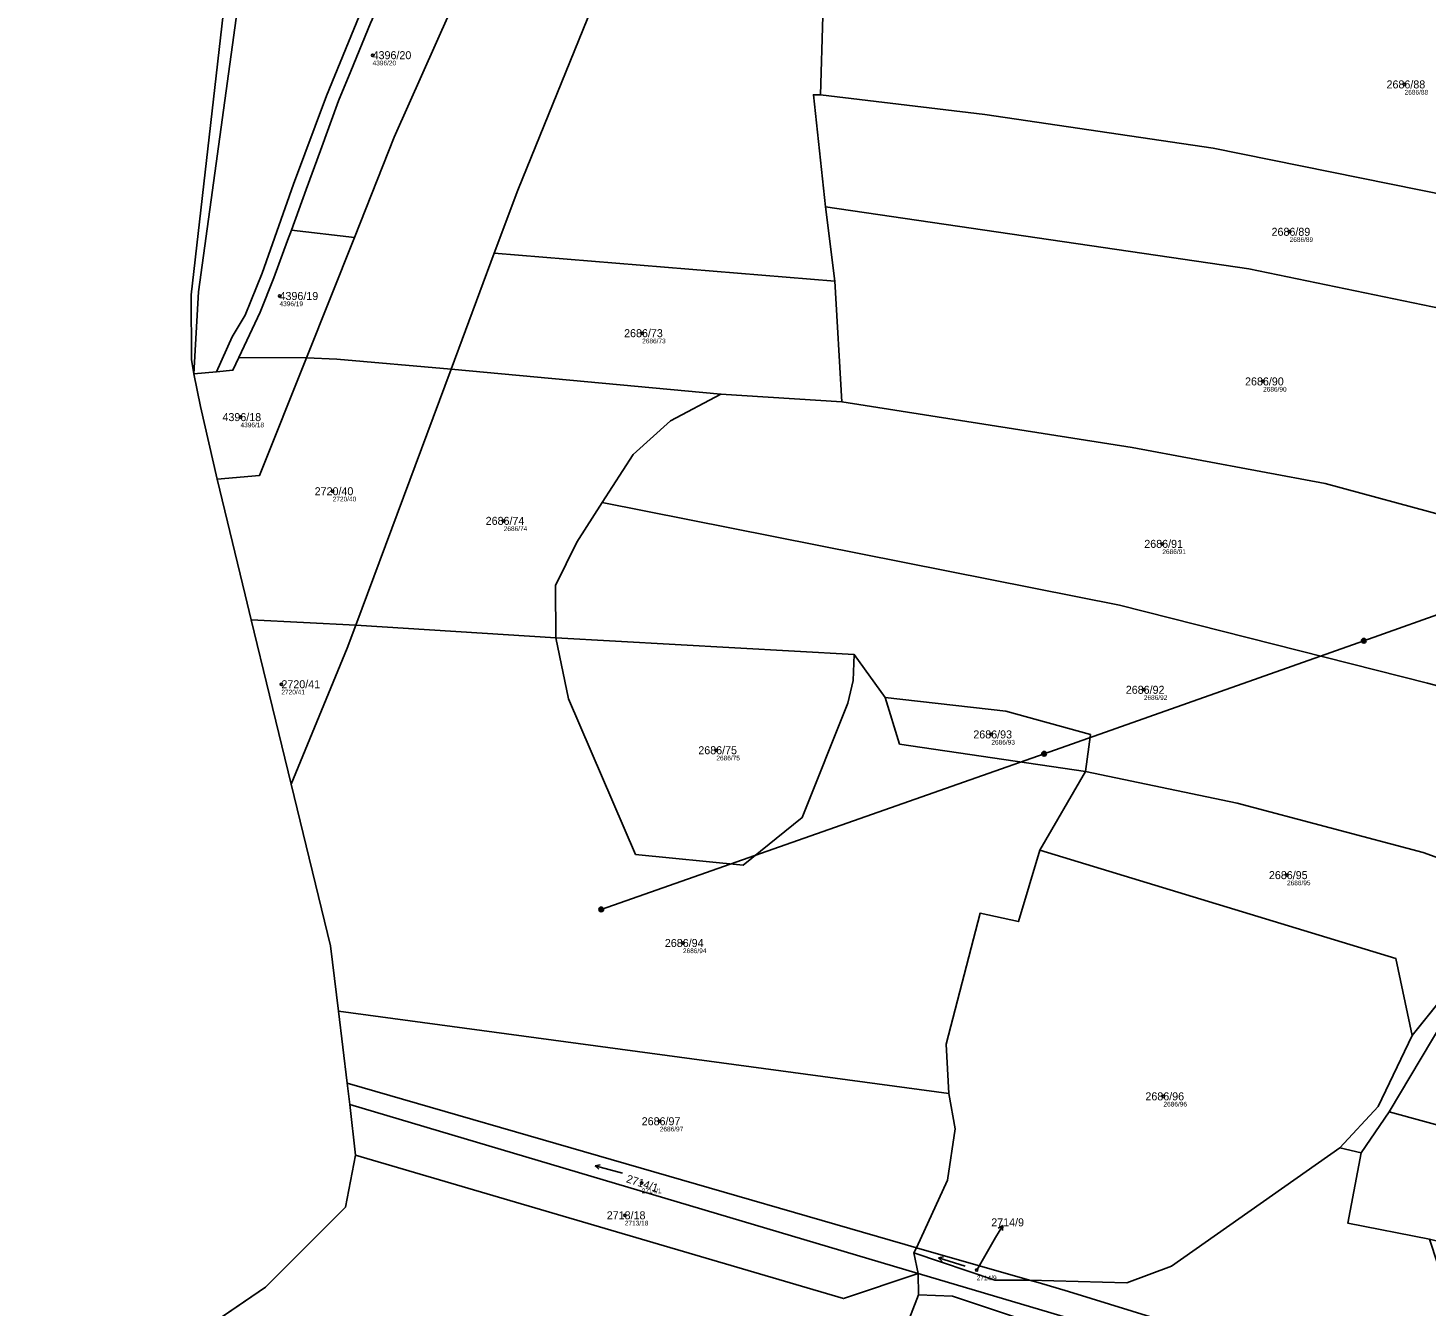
# Model space of a CAD drawing. Extents: x -739214 to -733252, y -1147612 to -1142842.
# Drawn here: x -737891.9 to -737595, y -1145670.6 to -1145399 of the extents above; entities that cross this region are included whole.
import ezdxf

# ---------------------------------------------------------------- set-up
doc = ezdxf.new("R2010")
doc.units = 0
for name, color, linetype in [('Definiční body', 7, 'Continuous'), ('Hranice parcel', 7, 'Continuous'), ('Parcelní čísla', 7, 'Continuous'), ('Polygon ku', 7, 'Continuous'), ('Polygon parcely', 7, 'Continuous'), ('Pop  PČ popisy', 7, 'Continuous'), ('Poz předměty', 7, 'Continuous'), ('Značky kultur', 7, 'Continuous')]:
    doc.layers.add(name, color=color, linetype=linetype)

msp = doc.modelspace()

# ---------------------------------------------------------------- linework, layer by layer
at = {"layer": 'Definiční body'}
for centre in [(-737818.71, -1145404.81), (-737599.53, -1145411.02), (-737623.95, -1145442.33), (-737838.48, -1145455.97), (-737761.46, -1145463.87), (-737629.58, -1145474.12), (-737846.76, -1145481.7), (-737827.18, -1145497.45), (-737790.86, -1145503.74), (-737650.98, -1145508.63), (-737838.08, -1145538.45), (-737654.91, -1145539.63), (-737687.29, -1145549.11), (-737745.7, -1145552.47), (-737624.51, -1145579), (-737752.8, -1145593.42), (-737650.74, -1145626), (-737757.72, -1145631.29), (-737761.57, -1145644.42), (-737765.14, -1145651.27), (-737690.41, -1145662.91)]:
    msp.add_circle(centre, 0.25, dxfattribs=at)
at = {"layer": 'Hranice parcel'}
for p, q in [((-737720.56, -1145452.83), (-737722.54, -1145437)), ((-737822.59, -1145443.55), (-737835.97, -1145442.01)), ((-737822.59, -1145443.55), (-737832.76, -1145469.11)), ((-737802.04, -1145471.5), (-737792.88, -1145446.87)), ((-737792.88, -1145446.87), (-737720.56, -1145452.83)), ((-737719.05, -1145478.43), (-737720.56, -1145452.83)), ((-737832.76, -1145469.11), (-737847.1, -1145469.03)), ((-737832.76, -1145469.11), (-737842.7, -1145494.1)), ((-737851.89, -1145472.08), (-737856.65, -1145472.54)), ((-737822.28, -1145525.91), (-737802.04, -1145471.5)), ((-737802.04, -1145471.5), (-737744.75, -1145476.81)), ((-737744.75, -1145476.81), (-737719.05, -1145478.43)), ((-737842.7, -1145494.1), (-737851.75, -1145494.89)), ((-737851.75, -1145494.89), (-737845.78, -1145519.46)), ((-737845.78, -1145519.46), (-737844.49, -1145524.74)), ((-737844.49, -1145524.74), (-737822.28, -1145525.91)), ((-737824.1, -1145530.8), (-737822.28, -1145525.91)), ((-737822.28, -1145525.91), (-737779.78, -1145528.62)), ((-737716.46, -1145532.13), (-737779.78, -1145528.62)), ((-737835.99, -1145559.66), (-737824.1, -1145530.8)), ((-737716.46, -1145532.13), (-737709.84, -1145541.29)), ((-737676.97, -1145573.7), (-737667.29, -1145556.98)), ((-737835.99, -1145559.66), (-737827.63, -1145594.05)), ((-737597.9, -1145613.1), (-737573.23, -1145582.26)), ((-737827.63, -1145594.05), (-737825.96, -1145607.93)), ((-737825.96, -1145607.93), (-737696.36, -1145625.39)), ((-737825.96, -1145607.93), (-737824.12, -1145623.17)), ((-737602.82, -1145629.32), (-737589.22, -1145606.52)), ((-737824.12, -1145623.17), (-737823.54, -1145627.71)), ((-737823.54, -1145627.71), (-737822.34, -1145638.53)), ((-737702.86, -1145663.63), (-737823.54, -1145627.71)), ((-737608.78, -1145638.02), (-737602.82, -1145629.32)), ((-737613.3, -1145636.92), (-737608.78, -1145638.02)), ((-737703.74, -1145659.28), (-737703.22, -1145658.15)), ((-737702.86, -1145663.63), (-737703.74, -1145659.28)), ((-737703.22, -1145658.15), (-737679.19, -1145665.04)), ((-737702.86, -1145663.63), (-737702.8, -1145668.15)), ((-737841.45, -1145666.51), (-737891.91, -1145700.99))]:
    msp.add_line(p, q, dxfattribs=at)
for points in [[(-737820.98, -1145248.16), (-737839.51, -1145313.31), (-737844.19, -1145341.49), (-737857.22, -1145455.75)], [(-737856.65, -1145472.54), (-737855.68, -1145455.08), (-737836.49, -1145315.56), (-737819.83, -1145253.02)], [(-737851.89, -1145472.08), (-737848.57, -1145464.61), (-737845.77, -1145460.03), (-737842.15, -1145451.1), (-737835.49, -1145432.24), (-737828.54, -1145413.46), (-737820.9, -1145394.95), (-737812.66, -1145376.69), (-737804.1, -1145358.6), (-737797.23, -1145339.83), (-737790.15, -1145321.11), (-737782.47, -1145302.64), (-737775.45, -1145283.92), (-737769.39, -1145267.89)], [(-737723.59, -1145413.2), (-737723.12, -1145396.55), (-737719.42, -1145368.93), (-737714.76, -1145352.17), (-737701.5, -1145354.38)], [(-737805.42, -1145365.82), (-737814.67, -1145388.16), (-737819.14, -1145398.03), (-737823.33, -1145408.23), (-737825.93, -1145414.53), (-737829.78, -1145425.05), (-737832.81, -1145433.33), (-737835.97, -1145442.01)], [(-737790.37, -1145368.76), (-737814.1, -1145422.2), (-737822.59, -1145443.55)], [(-737792.88, -1145446.87), (-737787.9, -1145433.5), (-737761.96, -1145369.63)], [(-737722.54, -1145437), (-737725.1, -1145413.2), (-737723.59, -1145413.2)], [(-737723.59, -1145413.2), (-737688.72, -1145417.44), (-737640.21, -1145424.55), (-737583.87, -1145435.95), (-737543.1, -1145448.28), (-737510.54, -1145463.81)], [(-737722.54, -1145437), (-737632.64, -1145450.18), (-737591.58, -1145458.72), (-737541.75, -1145472.73), (-737522.21, -1145480.38)], [(-737835.97, -1145442.01), (-737836.77, -1145444.19), (-737839.66, -1145452.12), (-737842.57, -1145459.44), (-737847.1, -1145469.03)], [(-737857.22, -1145455.75), (-737857.17, -1145469.44), (-737856.65, -1145472.54)], [(-737847.1, -1145469.03), (-737848.38, -1145471.74), (-737851.89, -1145472.08)], [(-737832.76, -1145469.11), (-737826.29, -1145469.39), (-737802.04, -1145471.5)], [(-737856.65, -1145472.54), (-737855.27, -1145479.41), (-737851.75, -1145494.89)], [(-737769.95, -1145499.87), (-737763.38, -1145489.61), (-737755.47, -1145482.51), (-737744.75, -1145476.81)], [(-737719.05, -1145478.43), (-737657.41, -1145488.14), (-737616.39, -1145495.81), (-737590.27, -1145502.9), (-737564.75, -1145511.61), (-737544.52, -1145520.75)], [(-737779.78, -1145528.62), (-737779.86, -1145517.46), (-737775.32, -1145508.26), (-737769.95, -1145499.87)], [(-737769.95, -1145499.87), (-737660.05, -1145521.67), (-737594.65, -1145538.21), (-737556.11, -1145548.41)], [(-737844.49, -1145524.74), (-737840.6, -1145540.74), (-737835.99, -1145559.66)], [(-737779.78, -1145528.62), (-737777.11, -1145541.57), (-737762.86, -1145574.62), (-737739.98, -1145576.92), (-737727.48, -1145566.78), (-737717.76, -1145542.47), (-737716.62, -1145537.65), (-737716.46, -1145532.13)], [(-737709.84, -1145541.29), (-737684.2, -1145544.15), (-737666.26, -1145549.14), (-737667.29, -1145556.98)], [(-737709.84, -1145541.29), (-737706.8, -1145551.18), (-737667.29, -1145556.98)], [(-737667.29, -1145556.98), (-737635.08, -1145563.73), (-737595.57, -1145574.22), (-737573.23, -1145582.26)], [(-737696.36, -1145625.39), (-737696.91, -1145614.89), (-737689.69, -1145587.09), (-737681.52, -1145588.86), (-737676.97, -1145573.7)], [(-737676.97, -1145573.7), (-737601.43, -1145596.68), (-737597.9, -1145613.1)], [(-737613.3, -1145636.92), (-737605.17, -1145628.13), (-737597.9, -1145613.1)], [(-737824.12, -1145623.17), (-737705.6, -1145657.47), (-737703.22, -1145658.15)], [(-737696.36, -1145625.39), (-737695, -1145632.88), (-737696.64, -1145643.79), (-737703.22, -1145658.15)], [(-737602.82, -1145629.32), (-737520.77, -1145651.77), (-737400.58, -1145678.49), (-737333.2, -1145691.3), (-737214.35, -1145710.13), (-737185.83, -1145716.79), (-737159.7, -1145725.21), (-737139.26, -1145734.98)], [(-737822.34, -1145638.53), (-737824.48, -1145649.51), (-737841.45, -1145666.51)], [(-737822.34, -1145638.53), (-737718.71, -1145668.96), (-737702.86, -1145663.63)], [(-737679.19, -1145665.04), (-737658.55, -1145665.61), (-737649.02, -1145662.11), (-737613.3, -1145636.92)], [(-737608.78, -1145638.02), (-737611.58, -1145652.96), (-737594.21, -1145656.35)], [(-737679.19, -1145665.04), (-737686.57, -1145665.05), (-737703.74, -1145659.28)], [(-737611.14, -1145716.76), (-737611.14, -1145701.1), (-737613.98, -1145694.1), (-737619.64, -1145689.1), (-737660.6, -1145676.2), (-737702.86, -1145663.63)], [(-737679.19, -1145665.04), (-737677.38, -1145665.56), (-737670.95, -1145667.46), (-737616.8, -1145684.16), (-737609.4, -1145690.18), (-737605.48, -1145699.2), (-737604.93, -1145717.85)], [(-737748.38, -1145708.23), (-737726.84, -1145698.64), (-737718.37, -1145693.53), (-737709.49, -1145685.57), (-737702.8, -1145668.15)], [(-737702.8, -1145668.15), (-737695.56, -1145668.48), (-737673.44, -1145675.79), (-737672.37, -1145683.37), (-737676.5, -1145694.97), (-737677.3, -1145705.14), (-737611.14, -1145716.76)]]:
    msp.add_lwpolyline(points, dxfattribs=at)
at = {"layer": 'Polygon ku'}
msp.add_lwpolyline([(-737844.19, -1145341.49), (-737857.22, -1145455.75), (-737857.17, -1145469.44), (-737856.65, -1145472.54), (-737855.27, -1145479.41), (-737851.75, -1145494.89), (-737845.78, -1145519.46), (-737844.49, -1145524.74), (-737840.6, -1145540.74), (-737835.99, -1145559.66), (-737827.63, -1145594.05), (-737825.96, -1145607.93), (-737824.12, -1145623.17), (-737823.54, -1145627.71), (-737822.34, -1145638.53), (-737824.48, -1145649.51), (-737841.45, -1145666.51), (-737891.91, -1145700.99)], dxfattribs=at)
at = {"layer": 'Polygon parcely'}
for points in [[(-737804.1, -1145358.6), (-737797.23, -1145339.83), (-737790.15, -1145321.11), (-737782.47, -1145302.64), (-737775.45, -1145283.92), (-737769.39, -1145267.89), (-737771.13, -1145267.35), (-737819.83, -1145253.02), (-737836.49, -1145315.56), (-737855.68, -1145455.08), (-737856.65, -1145472.54), (-737851.89, -1145472.08), (-737848.57, -1145464.61), (-737845.77, -1145460.03), (-737842.15, -1145451.1), (-737835.49, -1145432.24), (-737828.54, -1145413.46), (-737820.9, -1145394.95), (-737812.66, -1145376.69)], [(-737501.5, -1145453.26), (-737457.61, -1145416.9), (-737475.95, -1145408.95), (-737501.79, -1145402.86), (-737558.13, -1145387.45), (-737666.58, -1145363.91), (-737701.5, -1145354.38), (-737714.76, -1145352.17), (-737719.42, -1145368.93), (-737723.12, -1145396.55), (-737723.59, -1145413.2), (-737688.72, -1145417.44), (-737640.21, -1145424.55), (-737583.87, -1145435.95), (-737543.1, -1145448.28), (-737510.54, -1145463.81)], [(-737814.67, -1145388.16), (-737819.14, -1145398.03), (-737823.33, -1145408.23), (-737825.93, -1145414.53), (-737829.78, -1145425.05), (-737832.81, -1145433.33), (-737835.97, -1145442.01), (-737822.59, -1145443.55), (-737814.1, -1145422.2), (-737790.37, -1145368.76), (-737805.42, -1145365.82)], [(-737522.21, -1145480.38), (-737510.54, -1145463.81), (-737543.1, -1145448.28), (-737583.87, -1145435.95), (-737640.21, -1145424.55), (-737688.72, -1145417.44), (-737723.59, -1145413.2), (-737725.1, -1145413.2), (-737722.54, -1145437), (-737632.64, -1145450.18), (-737591.58, -1145458.72), (-737541.75, -1145472.73)], [(-737532.81, -1145497.63), (-737522.21, -1145480.38), (-737541.75, -1145472.73), (-737591.58, -1145458.72), (-737632.64, -1145450.18), (-737722.54, -1145437), (-737720.56, -1145452.83), (-737719.05, -1145478.43), (-737657.41, -1145488.14), (-737616.39, -1145495.81), (-737590.27, -1145502.9), (-737564.75, -1145511.61), (-737544.52, -1145520.75)], [(-737847.1, -1145469.03), (-737832.76, -1145469.11), (-737822.59, -1145443.55), (-737835.97, -1145442.01), (-737836.77, -1145444.19), (-737839.66, -1145452.12), (-737842.57, -1145459.44)], [(-737719.05, -1145478.43), (-737720.56, -1145452.83), (-737792.88, -1145446.87), (-737802.04, -1145471.5), (-737744.75, -1145476.81)], [(-737848.38, -1145471.74), (-737851.89, -1145472.08), (-737856.65, -1145472.54), (-737855.27, -1145479.41), (-737851.75, -1145494.89), (-737842.7, -1145494.1), (-737832.76, -1145469.11), (-737847.1, -1145469.03)], [(-737842.7, -1145494.1), (-737851.75, -1145494.89), (-737845.78, -1145519.46), (-737844.49, -1145524.74), (-737822.28, -1145525.91), (-737802.04, -1145471.5), (-737826.29, -1145469.39), (-737832.76, -1145469.11)], [(-737755.47, -1145482.51), (-737744.75, -1145476.81), (-737802.04, -1145471.5), (-737822.28, -1145525.91), (-737779.78, -1145528.62), (-737779.86, -1145517.46), (-737775.32, -1145508.26), (-737769.95, -1145499.87), (-737763.38, -1145489.61)], [(-737556.11, -1145548.41), (-737544.52, -1145520.75), (-737564.75, -1145511.61), (-737590.27, -1145502.9), (-737616.39, -1145495.81), (-737657.41, -1145488.14), (-737719.05, -1145478.43), (-737744.75, -1145476.81), (-737755.47, -1145482.51), (-737763.38, -1145489.61), (-737769.95, -1145499.87), (-737660.05, -1145521.67), (-737594.65, -1145538.21)], [(-737573.23, -1145582.26), (-737564.27, -1145566.85), (-737556.11, -1145548.41), (-737594.65, -1145538.21), (-737660.05, -1145521.67), (-737769.95, -1145499.87), (-737775.32, -1145508.26), (-737779.86, -1145517.46), (-737779.78, -1145528.62), (-737716.46, -1145532.13), (-737709.84, -1145541.29), (-737684.2, -1145544.15), (-737666.26, -1145549.14), (-737667.29, -1145556.98), (-737635.08, -1145563.73), (-737595.57, -1145574.22)], [(-737835.99, -1145559.66), (-737824.1, -1145530.8), (-737822.28, -1145525.91), (-737844.49, -1145524.74), (-737840.6, -1145540.74)], [(-737825.96, -1145607.93), (-737696.36, -1145625.39), (-737696.91, -1145614.89), (-737689.69, -1145587.09), (-737681.52, -1145588.86), (-737676.97, -1145573.7), (-737667.29, -1145556.98), (-737706.8, -1145551.18), (-737709.84, -1145541.29), (-737716.46, -1145532.13), (-737716.62, -1145537.65), (-737717.76, -1145542.47), (-737727.48, -1145566.78), (-737739.98, -1145576.92), (-737762.86, -1145574.62), (-737777.11, -1145541.57), (-737779.78, -1145528.62), (-737822.28, -1145525.91), (-737824.1, -1145530.8), (-737835.99, -1145559.66), (-737827.63, -1145594.05)], [(-737739.98, -1145576.92), (-737727.48, -1145566.78), (-737717.76, -1145542.47), (-737716.62, -1145537.65), (-737716.46, -1145532.13), (-737779.78, -1145528.62), (-737777.11, -1145541.57), (-737762.86, -1145574.62)], [(-737709.84, -1145541.29), (-737706.8, -1145551.18), (-737667.29, -1145556.98), (-737666.26, -1145549.14), (-737684.2, -1145544.15)], [(-737601.43, -1145596.68), (-737597.9, -1145613.1), (-737573.23, -1145582.26), (-737595.57, -1145574.22), (-737635.08, -1145563.73), (-737667.29, -1145556.98), (-737676.97, -1145573.7)], [(-737679.19, -1145665.04), (-737658.55, -1145665.61), (-737649.02, -1145662.11), (-737613.3, -1145636.92), (-737605.17, -1145628.13), (-737597.9, -1145613.1), (-737601.43, -1145596.68), (-737676.97, -1145573.7), (-737681.52, -1145588.86), (-737689.69, -1145587.09), (-737696.91, -1145614.89), (-737696.36, -1145625.39), (-737695, -1145632.88), (-737696.64, -1145643.79), (-737703.22, -1145658.15)], [(-737703.22, -1145658.15), (-737696.64, -1145643.79), (-737695, -1145632.88), (-737696.36, -1145625.39), (-737825.96, -1145607.93), (-737824.12, -1145623.17), (-737705.6, -1145657.47)], [(-737400.58, -1145678.49), (-737333.2, -1145691.3), (-737214.35, -1145710.13), (-737185.83, -1145716.79), (-737159.7, -1145725.21), (-737139.26, -1145734.98), (-737107.66, -1145714.11), (-737144.92, -1145698.54), (-737177.76, -1145689.31), (-737227.1, -1145681.01), (-737315.65, -1145669.34), (-737369.19, -1145660.88), (-737457.59, -1145643.96), (-737524.49, -1145628.52), (-737589.22, -1145606.52), (-737602.82, -1145629.32), (-737520.77, -1145651.77)], [(-737702.86, -1145663.63), (-737703.74, -1145659.28), (-737703.22, -1145658.15), (-737705.6, -1145657.47), (-737824.12, -1145623.17), (-737823.54, -1145627.71)], [(-737702.86, -1145663.63), (-737823.54, -1145627.71), (-737822.34, -1145638.53), (-737718.71, -1145668.96)], [(-737171.47, -1145755.23), (-737139.26, -1145734.98), (-737159.7, -1145725.21), (-737185.83, -1145716.79), (-737214.35, -1145710.13), (-737333.2, -1145691.3), (-737400.58, -1145678.49), (-737520.77, -1145651.77), (-737602.82, -1145629.32), (-737608.78, -1145638.02), (-737611.58, -1145652.96), (-737594.21, -1145656.35), (-737551.94, -1145667.13), (-737443.9, -1145691.77), (-737316.64, -1145719.35), (-737231.92, -1145733.14), (-737204.39, -1145740.83), (-737181.96, -1145749.65)], [(-737726.84, -1145698.64), (-737718.37, -1145693.53), (-737709.49, -1145685.57), (-737702.8, -1145668.15), (-737702.86, -1145663.63), (-737718.71, -1145668.96), (-737822.34, -1145638.53), (-737824.48, -1145649.51), (-737841.45, -1145666.51), (-737891.91, -1145700.99), (-737863.18, -1145730.85), (-737852.59, -1145710.34), (-737846.06, -1145700.88), (-737834.12, -1145689.5), (-737792.11, -1145705.16), (-737761.25, -1145714.74), (-737748.38, -1145708.23)], [(-737616.8, -1145684.16), (-737609.4, -1145690.18), (-737605.48, -1145699.2), (-737604.93, -1145717.85), (-737602.9, -1145718.21), (-737581.91, -1145722.08), (-737578.82, -1145722.6), (-737582.43, -1145702.05), (-737583.37, -1145689.86), (-737589.13, -1145671.86), (-737594.21, -1145656.35), (-737611.58, -1145652.96), (-737608.78, -1145638.02), (-737613.3, -1145636.92), (-737649.02, -1145662.11), (-737658.55, -1145665.61), (-737679.19, -1145665.04), (-737677.38, -1145665.56), (-737670.95, -1145667.46)], [(-737679.19, -1145665.04), (-737703.22, -1145658.15), (-737703.74, -1145659.28), (-737686.57, -1145665.05)], [(-737703.74, -1145659.28), (-737702.86, -1145663.63), (-737660.6, -1145676.2), (-737619.64, -1145689.1), (-737613.98, -1145694.1), (-737611.14, -1145701.1), (-737611.14, -1145716.76), (-737604.93, -1145717.85), (-737605.48, -1145699.2), (-737609.4, -1145690.18), (-737616.8, -1145684.16), (-737670.95, -1145667.46), (-737677.38, -1145665.56), (-737679.19, -1145665.04), (-737686.57, -1145665.05)], [(-737677.3, -1145705.14), (-737611.14, -1145716.76), (-737611.14, -1145701.1), (-737613.98, -1145694.1), (-737619.64, -1145689.1), (-737660.6, -1145676.2), (-737702.86, -1145663.63), (-737702.8, -1145668.15), (-737695.56, -1145668.48), (-737673.44, -1145675.79), (-737672.37, -1145683.37), (-737676.5, -1145694.97)], [(-737611.14, -1145719.86), (-737611.14, -1145716.76), (-737677.3, -1145705.14), (-737676.5, -1145694.97), (-737672.37, -1145683.37), (-737673.44, -1145675.79), (-737695.56, -1145668.48), (-737702.8, -1145668.15), (-737709.49, -1145685.57), (-737718.37, -1145693.53), (-737726.84, -1145698.64), (-737748.38, -1145708.23), (-737705.57, -1145723.56), (-737675.22, -1145730.76), (-737611.57, -1145741.52)]]:
    msp.add_lwpolyline(points, close=True, dxfattribs=at)
for points in [[(-737844.19, -1145341.49), (-737857.22, -1145455.75), (-737857.17, -1145469.44), (-737856.65, -1145472.54), (-737855.68, -1145455.08), (-737836.49, -1145315.56)], [(-737790.37, -1145368.76), (-737814.1, -1145422.2), (-737822.59, -1145443.55), (-737832.76, -1145469.11), (-737826.29, -1145469.39), (-737802.04, -1145471.5), (-737792.88, -1145446.87), (-737787.9, -1145433.5), (-737761.96, -1145369.63)], [(-737761.96, -1145369.63), (-737787.9, -1145433.5), (-737792.88, -1145446.87), (-737720.56, -1145452.83), (-737722.54, -1145437), (-737725.1, -1145413.2), (-737723.59, -1145413.2), (-737723.12, -1145396.55)], [(-737820.9, -1145394.95), (-737828.54, -1145413.46), (-737835.49, -1145432.24), (-737842.15, -1145451.1), (-737845.77, -1145460.03), (-737848.57, -1145464.61), (-737851.89, -1145472.08), (-737848.38, -1145471.74), (-737847.1, -1145469.03), (-737842.57, -1145459.44), (-737839.66, -1145452.12), (-737836.77, -1145444.19), (-737835.97, -1145442.01), (-737832.81, -1145433.33), (-737829.78, -1145425.05), (-737825.93, -1145414.53), (-737823.33, -1145408.23), (-737819.14, -1145398.03)], [(-737573.23, -1145582.26), (-737597.9, -1145613.1), (-737605.17, -1145628.13), (-737613.3, -1145636.92), (-737608.78, -1145638.02), (-737602.82, -1145629.32), (-737589.22, -1145606.52)]]:
    msp.add_lwpolyline(points, dxfattribs=at)
at = {"layer": 'Pop  PČ popisy'}
for p, q in [((-737686.39, -1145656.01), (-737684.89, -1145653.41)), ((-737684.89, -1145653.41), (-737685.82, -1145654.03)), ((-737684.89, -1145653.41), (-737684.96, -1145654.53)), ((-737690.41, -1145662.91), (-737686.39, -1145656.01))]:
    msp.add_line(p, q, dxfattribs=at)
at = {"layer": 'Poz předměty'}
for p, q in [((-737608.2, -1145529.21), (-737529.74, -1145501.33)), ((-737676.09, -1145553.21), (-737608.2, -1145529.21)), ((-737770.16, -1145586.28), (-737676.09, -1145553.21))]:
    msp.add_line(p, q, dxfattribs=at)
for centre, radius in [((-737608.2, -1145529.21), 0.5), ((-737608.2, -1145529.21), 0.4), ((-737608.2, -1145529.21), 0.3), ((-737608.2, -1145529.21), 0.2), ((-737608.2, -1145529.21), 0.1), ((-737676.09, -1145553.21), 0.5), ((-737676.09, -1145553.21), 0.4), ((-737676.09, -1145553.21), 0.3), ((-737676.09, -1145553.21), 0.2), ((-737676.09, -1145553.21), 0.1), ((-737770.16, -1145586.28), 0.5), ((-737770.16, -1145586.28), 0.4), ((-737770.16, -1145586.28), 0.3), ((-737770.16, -1145586.28), 0.2), ((-737770.16, -1145586.28), 0.1)]:
    msp.add_circle(centre, radius, dxfattribs=at)
at = {"layer": 'Značky kultur'}
for p, q in [((-737771.46, -1145640.76), (-737770.39, -1145640.53)), ((-737765.67, -1145642.31), (-737771.46, -1145640.76)), ((-737771.46, -1145640.76), (-737770.65, -1145641.5)), ((-737698.56, -1145660.32), (-737697.48, -1145660.13)), ((-737692.83, -1145662.07), (-737698.56, -1145660.32)), ((-737698.56, -1145660.32), (-737697.78, -1145661.08))]:
    msp.add_line(p, q, dxfattribs=at)

# ---------------------------------------------------------------- texts
at = {"layer": 'Definiční body'}
for s, p in [('4396/20', (-737818.71, -1145406.97)), ('2686/88', (-737599.53, -1145413.18)), ('2686/89', (-737623.95, -1145444.49)), ('4396/19', (-737838.48, -1145458.13)), ('2686/73', (-737761.46, -1145466.03)), ('2686/90', (-737629.58, -1145476.28)), ('4396/18', (-737846.76, -1145483.86)), ('2720/40', (-737827.18, -1145499.61)), ('2686/74', (-737790.86, -1145505.9)), ('2686/91', (-737650.98, -1145510.79)), ('2720/41', (-737838.08, -1145540.61)), ('2686/92', (-737654.91, -1145541.79)), ('2686/93', (-737687.29, -1145551.27)), ('2686/75', (-737745.7, -1145554.63)), ('2686/95', (-737624.51, -1145581.16)), ('2686/94', (-737752.8, -1145595.58)), ('2686/96', (-737650.74, -1145628.16)), ('2686/97', (-737757.72, -1145633.45)), ('2714/1', (-737761.57, -1145646.58)), ('2713/18', (-737765.14, -1145653.43)), ('2714/9', (-737690.41, -1145665.07))]:
    msp.add_text(s, height=1, dxfattribs=at).set_placement(p)
at = {"layer": 'Parcelní čísla'}
for s, p in [('4396/20', (-737818.71, -1145405.66)), ('2686/88', (-737603.37, -1145411.87)), ('2686/89', (-737627.79, -1145443.18)), ('4396/19', (-737838.48, -1145456.82)), ('2686/73', (-737765.3, -1145464.72)), ('2686/90', (-737633.42, -1145474.97)), ('4396/18', (-737850.6, -1145482.55)), ('2720/40', (-737831.02, -1145498.3)), ('2686/74', (-737794.7, -1145504.59)), ('2686/91', (-737654.82, -1145509.48)), ('2720/41', (-737838.08, -1145539.3)), ('2686/92', (-737658.75, -1145540.48)), ('2686/93', (-737691.13, -1145549.96)), ('2686/75', (-737749.54, -1145553.32)), ('2686/95', (-737628.35, -1145579.85)), ('2686/94', (-737756.64, -1145594.27)), ('2686/96', (-737654.58, -1145626.85)), ('2686/97', (-737761.56, -1145632.14)), ('2713/18', (-737768.98, -1145652.12)), ('2714/9', (-737687.32, -1145653.62))]:
    msp.add_text(s, height=1.7, dxfattribs=at).set_placement(p)
msp.add_text('2714/1', height=1.7, rotation=342, dxfattribs=at).set_placement((-737764.98, -1145644.21))

doc.saveas('drawing.dxf')
